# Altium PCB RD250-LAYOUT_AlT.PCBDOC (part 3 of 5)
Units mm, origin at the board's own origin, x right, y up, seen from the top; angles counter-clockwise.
Board outline 318.5 x 135 mm, 6 copper layers (TOP, Mid-Layer 1, Mid-Layer 2, Mid-Layer 3, Mid-Layer 4, BOTTOM), stack 1.422 mm thick; 550 components, 251 nets, 1350 pads, 626 vias.
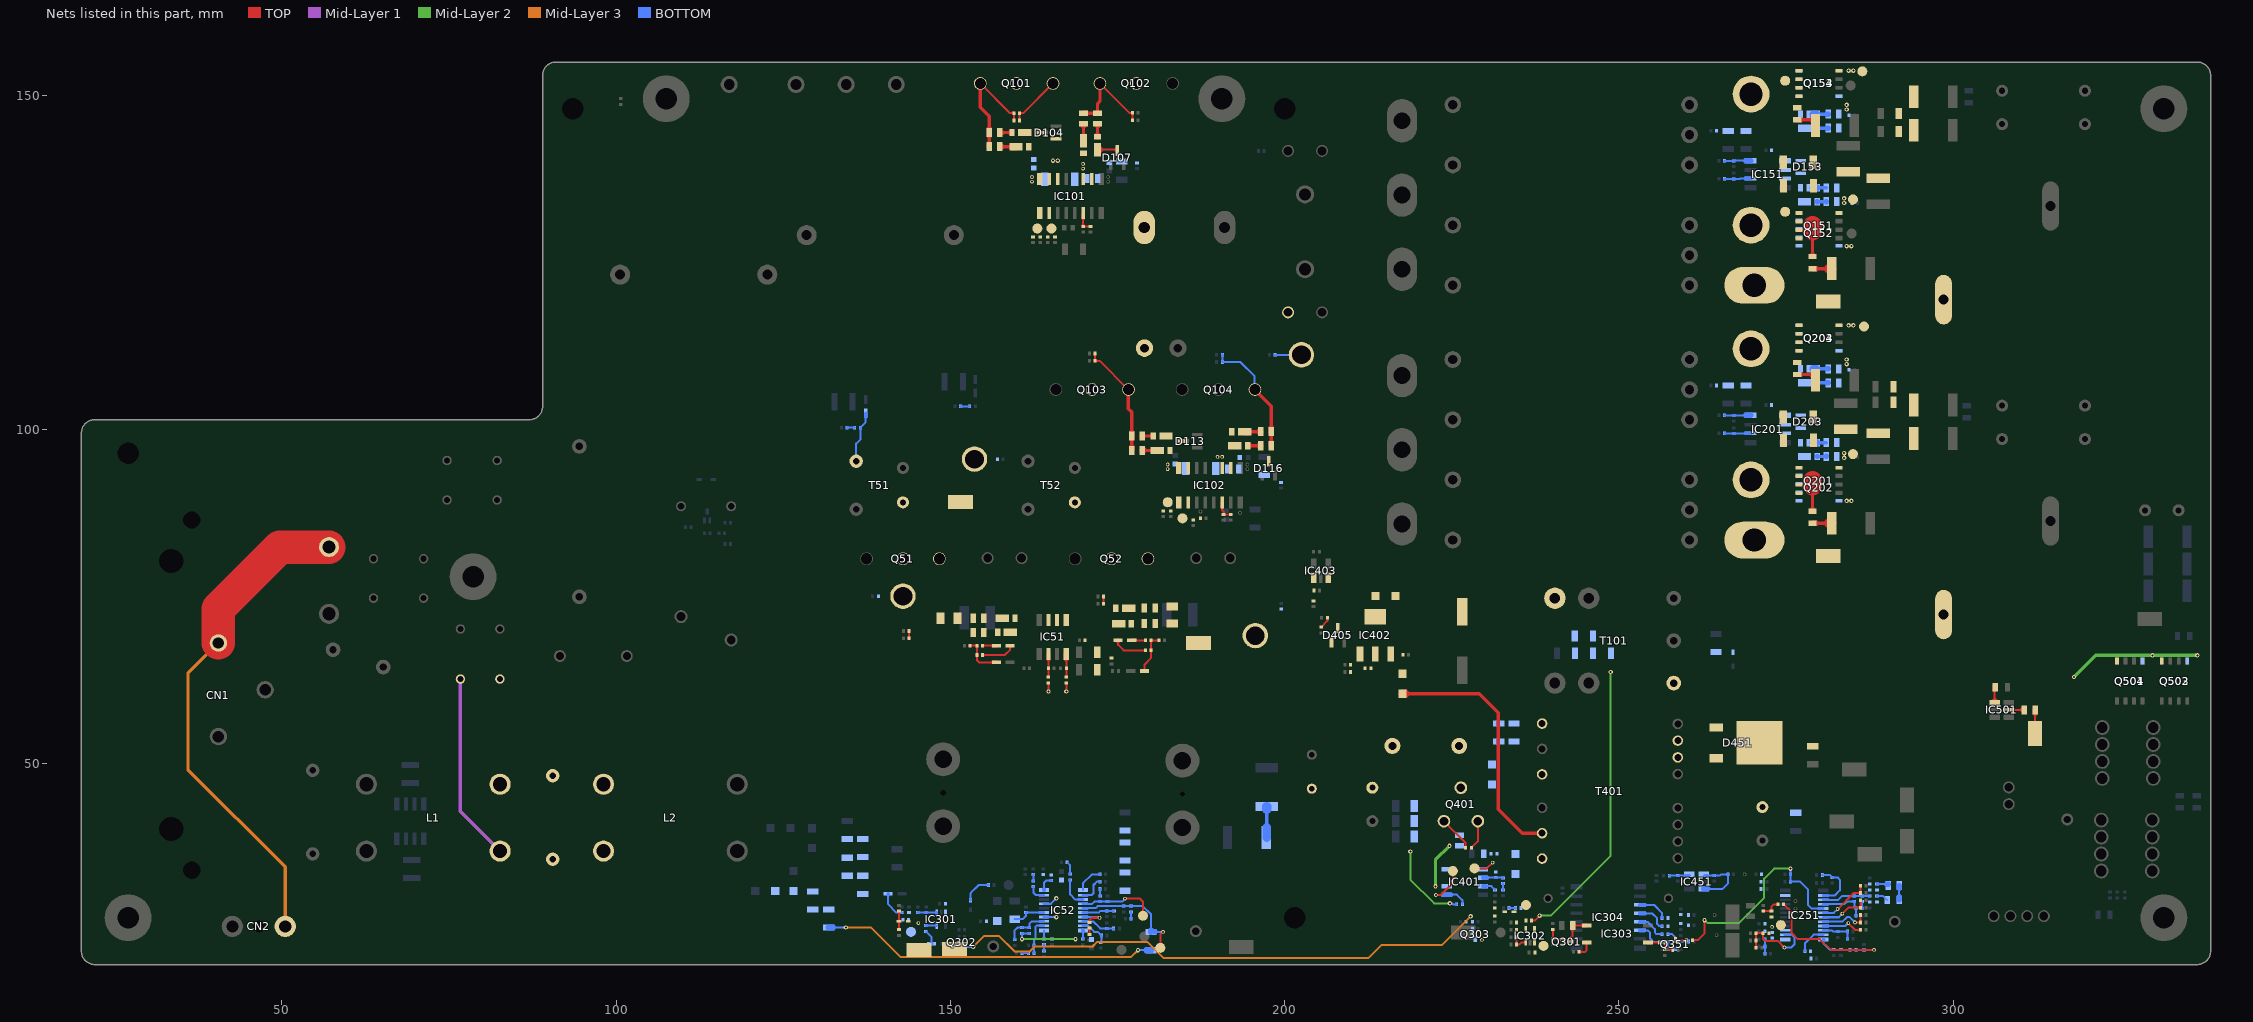
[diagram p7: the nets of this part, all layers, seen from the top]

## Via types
v1: diameter 0.65, hole 0.3, TOP to BOTTOM, 626 vias

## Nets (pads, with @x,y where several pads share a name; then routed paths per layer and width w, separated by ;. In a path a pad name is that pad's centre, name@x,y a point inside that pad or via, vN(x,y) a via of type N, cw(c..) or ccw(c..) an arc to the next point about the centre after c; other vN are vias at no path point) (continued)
SIG16: C60.2 R61.1 | length 1.3
  BOTTOM w0.3: C60.2@151.703,103.5 R61.1@152.697,103.5
  BOTTOM w0.45: C60.2@151.525,103.5 C60.2@151.703,103.5 ; R61.1@152.697,103.5 R61.1@152.875,103.5
SIG18: Q52.D T52.3
SIG20: D58.A R53.2 T51.1 | length 7.8
  BOTTOM w0.3: T51.1@135.9,95.3 135.9,97.9 136.525,98.525 R53.2@136.525,100.122 ; R53.2@136.525,100.3 137.31,101.085 D58.A@137.31,101.873
  BOTTOM w0.45: R53.2@136.525,100.122 R53.2@136.525,100.3
  BOTTOM w0.55: D58.A@137.31,101.873 D58.A@137.31,102.475
SIG21: C58.2 R53.1 | length 1.2
  BOTTOM w0.3: C58.2@134.703,100.3 R53.1@135.497,100.3
  BOTTOM w0.45: C58.2@134.525,100.3 C58.2@134.703,100.3 ; R53.1@135.497,100.3 R53.1@135.675,100.3
SIG22: Q51.D T51.3
SIG0022: C54.2 IC51.2 R97.2 | length 3.5
  TOP w0.3: C54.2@164.665,64.443 IC51.2@164.665,65.623 ; R97.2@164.675,63.163 C54.2@164.675,64.122
  TOP w0.43: C54.2@164.665,64.26 C54.2@164.665,64.443
  TOP w0.45: R97.2@164.675,62.975 R97.2@164.675,63.163 ; C54.2@164.675,64.122 C54.2@164.675,64.3
  TOP w0.55: IC51.2@164.665,65.623 IC51.2@164.665,66.443
SIG23: L54.1 R62.2 R63.2
SIG0023: C53.2 IC51.4 R98.2 | length 3.5
  TOP w0.3: R98.2@167.325,63.163 C53.2@167.325,64.122 ; C53.2@167.342,64.446 IC51.4@167.342,65.772
  TOP w0.415: C53.2@167.342,64.267 C53.2@167.342,64.446
  TOP w0.45: R98.2@167.325,62.975 R98.2@167.325,63.163 ; C53.2@167.325,64.122 C53.2@167.325,64.3
  TOP w0.825: IC51.4@167.342,65.772 IC51.4@167.342,66.443
SIG24: C61.2 D67.A R65.2 R66.2 | length 6.2
  TOP w0.3: D67.A@179.025,64.01 179.025,64.875 180.025,65.875 R65.2@180.025,66.822 ; R65.2@180.025,67.178 R66.2@180.025,68.322 ; R66.2@180.203,68.5 C61.2@180.997,68.5
  TOP w0.45: R65.2@180.025,66.822 R65.2@180.025,67 R65.2@180.025,67.178 ; R66.2@180.025,68.322 R66.2@180.025,68.5 R66.2@180.203,68.5 ; C61.2@180.997,68.5 C61.2@181.175,68.5
  TOP w0.55: D67.A@179.025,63.9 D67.A@179.025,64.01
SIG0024: C76.1 R91.2 | length 2
  BOTTOM w0.3: R91.2@167.425,35.3 167.9,34.825 C76.1@167.9,33.653
  BOTTOM w0.45: C76.1@167.9,33.525 C76.1@167.9,33.653
SIG25: C59.2 D62.A R57.2 R58.2 | length 6.3
  TOP w0.3: C59.2@153.09,67.7 R58.2@153.81,67.7 ; R57.2@153.975,66.122 153.975,65.5 154.275,65.2 D62.A@156.273,65.2 ; R57.2@153.975,66.478 R58.2@153.975,67.522
  TOP w0.45: C59.2@152.925,67.7 C59.2@153.09,67.7 ; R58.2@153.81,67.7 R58.2@153.975,67.7 R58.2@153.975,67.522 ; R57.2@153.975,66.122 R57.2@153.975,66.3 R57.2@153.975,66.478
  TOP w0.55: D62.A@156.273,65.2 D62.A@156.875,65.2
SIG0025: C74.1 R90.2 | length 1
  BOTTOM w0.3: R90.2@160.84,21.7 C74.1@161.56,21.7
  BOTTOM w0.45: R90.2@160.725,21.7 R90.2@160.84,21.7 ; C74.1@161.56,21.7 C74.1@161.675,21.7
SIG0026: C70.2 IC52.13 R86.2 R87.2 | length 6.7
  BOTTOM w0.3: C70.2@159.6,23.903 159.6,25.1 160.025,25.525 R86.2@160.7,25.525 ; R86.2@160.878,25.525 R87.2@161.622,25.525 ; R87.2@161.8,25.703 161.8,26.1 162.175,26.475 IC52.13@163.343,26.475
  BOTTOM w0.4: IC52.13@163.343,26.475 IC52.13@163.975,26.475
  BOTTOM w0.45: C70.2@159.6,23.725 C70.2@159.6,23.903 ; R86.2@160.7,25.525 R86.2@160.878,25.525 ; R87.2@161.622,25.525 R87.2@161.8,25.525 R87.2@161.8,25.703
SIG27: L53.1 R54.2 R55.2
SIG0027: C67.2 C68.2 D68.C IC52.15 R85.2 | length 5.1
  BOTTOM w0.3: C67.2@159.6,26.8 160.8,26.8 161.3,27.3 C68.2@161.3,27.66 ; C68.2@161.478,27.775 IC52.15@163.276,27.775
  BOTTOM w0.4: IC52.15@163.276,27.775 IC52.15@163.975,27.775
  BOTTOM w0.45: C68.2@161.3,27.66 C68.2@161.3,27.775 C68.2@161.478,27.775
SIG0028: R83.1 R84.2 | length 1
  BOTTOM w0.3: R83.1@162.4,32.64 R84.2@162.4,33.36
  BOTTOM w0.45: R83.1@162.4,32.525 R83.1@162.4,32.64 ; R84.2@162.4,33.36 R84.2@162.4,33.475
SIG0029: IC52.19 R83.2 | length 2.6
  BOTTOM w0.3: R83.2@162.4,31.585 162.4,30.775 162.8,30.375 IC52.19@163.276,30.375
  BOTTOM w0.4: IC52.19@163.276,30.375 IC52.19@163.975,30.375
  BOTTOM w0.45: R83.2@162.4,31.585 R83.2@162.4,31.675
SIG30: D59.A D60.C D61.C IC51.7 R57.1 | length 5
  TOP w0.3: R57.1@155.003,66.3 158.125,66.3 158.925,67.1 D61.C@158.925,67.54
  TOP w0.45: R57.1@154.825,66.3 R57.1@155.003,66.3
  TOP w0.55: D61.C@158.925,67.54 D61.C@158.925,67.7
SIG0057: IC251.2 R272.1 R273.2 | length 7.3
  BOTTOM w0.3: R273.2@280.603,33.4 281.525,33.4 R272.1@281.9,33.025 ; IC251.2@281.324,30.325 282.275,30.325 283.05,31.1 283.05,32.675 282.7,33.025 R272.1@282.078,33.025
  BOTTOM w0.4: IC251.2@280.562,30.325 IC251.2@281.324,30.325
  BOTTOM w0.45: R273.2@280.425,33.4 R273.2@280.603,33.4 ; R272.1@281.9,33.025 R272.1@282.078,33.025
SIG0058: C256.1 R286.1 | length 1
  BOTTOM w0.3: C256.1@286.325,28.553 R286.1@286.325,29.312
  BOTTOM w0.4: R286.1@286.325,29.312 R286.1@286.325,29.425
  BOTTOM w0.45: C256.1@286.325,28.4 C256.1@286.325,28.553
SIG0059: C257.1 C258.1 IC251.3 R286.2 R289.1 R290.2 | length 8.9
  BOTTOM w0.3: IC251.3@281.324,29.675 282.775,29.675 283.375,30.275 C257.1@285.022,30.275 ; C257.1@285.378,30.275 R286.2@286.222,30.275 ; R286.2@286.578,30.275 R289.1@287.322,30.275 ; R290.2@288.703,30.225 289.525,30.225 C258.1@290.1,29.65
  BOTTOM w0.4: IC251.3@280.562,29.675 IC251.3@281.324,29.675
  BOTTOM w0.45: C257.1@285.022,30.275 C257.1@285.2,30.275 C257.1@285.378,30.275 ; R286.2@286.222,30.275 R286.2@286.4,30.275 R286.2@286.578,30.275 ; R289.1@287.322,30.275 R289.1@287.5,30.275 ; R290.2@288.6,30.225 R290.2@288.703,30.225
SIG100: D64.C R63.1
SIG101: D65.A R62.1
SIG102: D64.A D65.C D66.C IC51.5 R65.1 | length 5.1
  TOP w0.3: D66.C@175.075,68.303 175.075,67.825 175.9,67 R65.1@178.997,67
  TOP w0.45: R65.1@178.997,67 R65.1@179.175,67
  TOP w0.55: D66.C@175.075,68.303 D66.C@175.075,68.5
SIG104: C55.2 C56.2 C57.2 IC51.6 R51.2
SIG105: D60.A R54.1
SIG106: D59.C R55.1
SIG115: C204.2 CN201.1 D207.A Q201.5 Q201.6 Q201.7 Q201.8 Q202.5 Q202.6 Q202.7 Q202.8 | length 4.6
  TOP w0.5: C204.2@278.95,88.106 278.95,91.646
  TOP w0.8: C204.2@278.95,87.8 C204.2@278.95,88.106
  TOP w2.9: 278.95,91.646 278.95,92.4
SIG122: C509.1 IC501.1 | length 2.5
  TOP w0.3: IC501.1@306.175,59.436 C509.1@306.175,60.938
  TOP w0.55: C509.1@306.175,60.938 C509.1@306.175,61.7
  TOP w0.825: IC501.1@306.175,59.187 IC501.1@306.175,59.436
SIG136: IC501.5 R504.1 | length 2.3
  TOP w0.3: IC501.5@309.027,58.1 R504.1@310.401,58.1
  TOP w0.55: IC501.5@308.325,58.1 IC501.5@309.027,58.1
  TOP w0.83: R504.1@310.401,58.1 R504.1@310.65,58.1
SIG141: DP502.1 Q501.4 Q502.4 Q503.4 Q504.4 R504.2 | length 23.3
  TOP w0.3: DP502.1@312.25,55.35 R504.2@312.25,57.591
  TOP w0.83: R504.2@312.25,57.591 R504.2@312.25,58.1
  TOP w2.1: DP502.1@312.25,54.55 DP502.1@312.25,55.35
  Mid-Layer 2 w0.5: v1(318.05,63) 321.3,66.25 v1(329.8,66.25) v1(336.5,66.25)
SIG193: CN1.1 CN2.1 F1.1 | length 75.8
  TOP w5: CN1.1@40.5,68.1 40.5,73.25 49.7,82.45 F1.1@57.05,82.45
  Mid-Layer 3 w0.5: CN1.1@40.5,68.1 35.95,63.55 35.95,49.15 50.5,34.6 CN2.1@50.5,25.7
SIG199: C4.2 C6.2 L1.2 L2.1
SIG200: C5.2 C6.1 L1.3 L2.4 | length 28.2
  Mid-Layer 1 w0.5: C5.2@76.7,62.7 76.7,42.913 80.363,39.25 L1.3@82.643,36.97
SIG00210: R93.1 R94.2
SIG00211: C64.2 DP56.1 IC52.5 pad.@181.8,24.9 R72.1 R73.2 | length 17.8
  TOP w0.3: DP56.1@181.4,22.5 181.4,24.484 cw(c181.438,24.484) 181.411,24.511 pad.@181.8,24.9
  BOTTOM w0.3: IC52.5@170.524,28.425 171.725,28.425 172.025,28.725 C64.2@175.71,28.725 ; C64.2@175.978,28.725 R73.2@176.822,28.725 ; R73.2@177.178,28.725 178.775,28.725 180,27.5 R72.1@180,25.116 ; R72.1@180.54,24.9 pad.@181.8,24.9
  BOTTOM w0.4: IC52.5@169.825,28.425 IC52.5@170.524,28.425
  BOTTOM w0.45: C64.2@175.71,28.725 C64.2@175.9,28.725 C64.2@175.978,28.725 ; R73.2@176.822,28.725 R73.2@177,28.725 R73.2@177.178,28.725
  BOTTOM w0.82: R72.1@180.05,24.9 R72.1@180.54,24.9
  BOTTOM w0.92: R72.1@180,24.85 R72.1@180,25.116
SIG00212: R95.1 R96.2 | length 1
  BOTTOM w0.3: R95.1@172.4,30.428 R96.2@172.4,31.187
  BOTTOM w0.4: R96.2@172.4,31.187 R96.2@172.4,31.3
  BOTTOM w0.45: R95.1@172.4,30.275 R95.1@172.4,30.428
SIG00213: IC52.7 pad.@172.3,27 R81.2 | length 4.5
  TOP w0.3: R81.2@170.8,26.325 170.8,26.652 171.148,27 pad.@172.3,27
  BOTTOM w0.3: IC52.7@170.524,27.125 171.6,27.125 171.725,27 pad.@172.3,27
  BOTTOM w0.4: IC52.7@169.825,27.125 IC52.7@170.524,27.125
SIG00214: C77.2 DP60.1 IC52.4 pad.@176.1,29.85 R94.1 R95.2 | length 11.6
  TOP w0.3: pad.@176.1,29.85 178.35,29.85 178.8,29.4 DP60.1@178.8,27.3
  BOTTOM w0.3: IC52.4@170.482,29.075 171.2,29.075 171.55,29.425 R95.2@172.222,29.425 ; R95.2@172.578,29.425 C77.2@173.322,29.425 ; C77.2@173.615,29.425 175.675,29.425 pad.@176.1,29.85
  BOTTOM w0.4: IC52.4@169.825,29.075 IC52.4@170.482,29.075
  BOTTOM w0.45: R95.2@172.222,29.425 R95.2@172.4,29.425 R95.2@172.578,29.425 ; C77.2@173.322,29.425 C77.2@173.5,29.425 C77.2@173.615,29.425
SIG00215: R81.1 R82.2 | length 1
  TOP w0.3: R82.2@170.8,24.64 R81.1@170.8,25.36
  TOP w0.45: R82.2@170.8,24.525 R82.2@170.8,24.64 ; R81.1@170.8,25.36 R81.1@170.8,25.475
SIG00216: R77.1 R78.2
SIG00217: R73.1 R74.2 | length 1
  BOTTOM w0.3: R74.2@177.025,27.003 R73.1@177.025,27.812
  BOTTOM w0.45: R74.2@177.025,26.85 R74.2@177.025,27.003 ; R73.1@177.025,27.812 R73.1@177.025,27.875
SIG00218: R70.1 R71.2
SIG00219: C69.2 IC52.10 R86.1 R87.1 R88.2 | length 11.2
  Mid-Layer 2 w0.3: v1(160.7,23.8) v1(168.7,23.8)
  BOTTOM w0.3: v1(160.7,23.8) R86.1@160.7,24.597 ; R86.1@160.878,24.675 R87.1@161.622,24.675 ; R88.2@169.825,24.025 IC52.10@169.825,24.943
  BOTTOM w0.4: R88.2@169.825,23.85 R88.2@169.825,24.025
  BOTTOM w0.45: R86.1@160.7,24.597 R86.1@160.7,24.675 R86.1@160.878,24.675 ; R87.1@161.622,24.675 R87.1@161.8,24.675
  BOTTOM w0.6: IC52.10@169.825,24.943 IC52.10@169.825,25.075
SIG00220: C73.2 C74.2 IC52.12 | length 5.4
  BOTTOM w0.3: C74.2@162.525,21.878 C73.2@162.525,22.722 ; C73.2@162.525,22.902 162.525,23.625 162.7,23.8 162.7,25.625 162.9,25.825 IC52.12@163.276,25.825
  BOTTOM w0.4: IC52.12@163.276,25.825 IC52.12@163.975,25.825
  BOTTOM w0.45: C74.2@162.525,21.7 C74.2@162.525,21.878 ; C73.2@162.525,22.722 C73.2@162.525,22.9 C73.2@162.525,22.902
SIG00221: C71.2 C72.2 IC52.11 | length 2.5
  BOTTOM w0.3: IC52.11@163.975,25.075 163.975,24.125 164,24.1 C72.2@164,23.825 ; C72.2@164.178,23.825 C71.2@165.022,23.825
  BOTTOM w0.45: C72.2@164,23.825 C72.2@164.178,23.825 ; C71.2@165.022,23.825 C71.2@165.2,23.825
SIG00222: R71.1 R72.2 | length 50.5
  Mid-Layer 3 w0.3: v1(134.35,25.55) 138.1,25.55 142.55,21.1 177,21.1 v1(178.05,22.15)
  BOTTOM w0.3: R71.1@132.456,25.55 v1(134.35,25.55) ; v1(178.05,22.15) R72.2@179.344,22.15
  BOTTOM w0.92: R71.1@131.8,25.55 R71.1@132.456,25.55 ; R72.2@179.344,22.15 R72.2@180,22.15
SIG00223: IC52.6 R79.2 R80.2 | length 4.7
  BOTTOM w0.3: IC52.6@170.458,27.775 172.175,27.775 172.425,28.025 R79.2@173.222,28.025 ; R79.2@173.573,28.025 R80.2@174.227,28.025
  BOTTOM w0.4: IC52.6@169.825,27.775 IC52.6@170.458,27.775
  BOTTOM w0.45: R79.2@173.222,28.025 R79.2@173.4,28.025 R79.2@173.573,28.025 ; R80.2@174.227,28.025 R80.2@174.4,28.025
SIG00224: IC52.20 R77.2 | length 2.4
  BOTTOM w0.3: IC52.20@163.975,31.331 163.975,32.2 164.35,32.575 R77.2@164.922,32.575
  BOTTOM w0.45: R77.2@164.922,32.575 R77.2@165.1,32.575
  BOTTOM w0.6: IC52.20@163.975,31.125 IC52.20@163.975,31.331
SIG00225: C63.2 IC52.8 R69.2 | length 5.1
  BOTTOM w0.3: IC52.8@170.524,26.475 171.325,26.475 172.4,25.4 C63.2@173.37,25.4 ; C63.2@173.565,25.375 R69.2@174.325,25.375
  BOTTOM w0.4: IC52.8@169.825,26.475 IC52.8@170.524,26.475 ; C63.2@173.37,25.4 C63.2@173.4,25.4 ; R69.2@174.325,25.375 R69.2@174.45,25.375
  BOTTOM w0.45: C63.2@173.4,25.375 C63.2@173.565,25.375
SIG00226: C65.2 IC52.1 | length 4.1
  BOTTOM w0.3: IC52.1@169.825,31.125 169.825,32.08 cw(c170.025,32.08) 169.884,32.221 171.104,33.442 cw(c171.245,33.3) 171.245,33.5 C65.2@172.187,33.5
  BOTTOM w0.45: C65.2@172.187,33.5 C65.2@172.375,33.5
SIG00227: R92.1 R93.2
SIG00228: IC52.2 R76.2 | length 4.1
  BOTTOM w0.3: IC52.2@170.524,30.375 171.1,30.375 171.4,30.675 171.4,31.9 171.9,32.4 R76.2@172.347,32.4
  BOTTOM w0.4: IC52.2@169.825,30.375 IC52.2@170.524,30.375
  BOTTOM w0.45: R76.2@172.347,32.4 R76.2@172.375,32.4
SIG00229: C75.2 C76.2 IC52.3 | length 4.4
  BOTTOM w0.3: C76.2@167.9,32.497 167.9,30.5 168.675,29.725 IC52.3@169.126,29.725
  BOTTOM w0.4: IC52.3@169.126,29.725 IC52.3@169.825,29.725
  BOTTOM w0.45: C76.2@167.9,32.497 C76.2@167.9,32.675
SIG00230: C72.1 R89.2 | length 1
  BOTTOM w0.3: R89.2@164,22.14 C72.1@164,22.86
  BOTTOM w0.45: R89.2@164,22.025 R89.2@164,22.14 ; C72.1@164,22.86 C72.1@164,22.975
SIG00231: C62.2 IC52.9 R68.2 | length 4.4
  BOTTOM w0.3: IC52.9@170.355,25.825 170.575,25.825 171.5,24.9 172.025,24.9 R68.2@172.575,24.35 ; C62.2@172.575,23.437 R68.2@172.575,24.198
  BOTTOM w0.4: IC52.9@169.825,25.825 IC52.9@170.355,25.825 ; C62.2@172.575,23.325 C62.2@172.575,23.437
  BOTTOM w0.45: R68.2@172.575,24.198 R68.2@172.575,24.35
SIG00232: D53.C D54.C R70.2
SIG00233: DP57.1 IC52.17 R98.1 | length 3.5
  TOP w0.3: v1(167.325,60.85) R98.1@167.325,61.938
  TOP w0.45: R98.1@167.325,61.938 R98.1@167.325,62.125
  BOTTOM w0.3: IC52.17@164.674,29.075 165.025,29.075 v1(165.85,29.9)
  BOTTOM w0.4: IC52.17@163.975,29.075 IC52.17@164.674,29.075
SIG00234: DP58.1 IC52.14 R97.1 | length 3.2
  TOP w0.3: v1(164.675,60.85) R97.1@164.675,61.938
  TOP w0.45: R97.1@164.675,61.938 R97.1@164.675,62.125
  BOTTOM w0.3: IC52.14@164.505,27.125 164.975,27.125 165,27.1 v1(165.85,27.1)
  BOTTOM w0.4: IC52.14@163.975,27.125 IC52.14@164.505,27.125
SIG00331: R101.1 R102.2 | length 4.6
  BOTTOM w0.5: R102.2@197.3,40.498 R101.1@197.3,43.228
  BOTTOM w1.31: R102.2@197.3,39 R102.2@197.3,40.498
  BOTTOM w1.405: R101.1@197.3,43.228 R101.1@197.3,43.647
SIG00332: D251.A R251.2 T101.5
SIG00333: D105.A D106.C D107.C IC101.10 | length 3
  TOP w0.3: D106.C@172.3,141.9 D107.C@174.737,141.9
  TOP w0.55: D107.C@174.737,141.9 D107.C@174.95,141.9
  TOP w1.1: D106.C@172,141.9 D106.C@172.3,141.9
SIG00334: C108.2 D101.C IC101.16 pad.@162.2,137.1 pad.@162.2,137.8
SIG00335: D101.A R107.1
SIG00336: C106.2 C107.2 IC101.11 pad.@169.85,139.05 pad.@169.85,139.75 R106.2 R107.2
SIG00337: D105.C R111.1 | length 2.5
  TOP w0.5: D105.C@169.9,143.845 R111.1@169.9,145.438
  TOP w0.83: R111.1@169.9,145.438 R111.1@169.9,145.75
  TOP w1.1: D105.C@169.9,143.25 D105.C@169.9,143.845
SIG00338: D106.A R112.1 | length 2
  TOP w0.5: D106.A@172,144.106 R112.1@172,145.439
  TOP w0.8: D106.A@172,143.8 D106.A@172,144.106
  TOP w0.83: R112.1@172,145.439 R112.1@172,145.75
SIG00339: D102.A D103.C D104.C IC101.15
SIG00340: D103.A R109.1 | length 1.8
  TOP w0.5: R109.1@157.636,144.45 D103.A@158.94,144.45
  TOP w0.8: D103.A@158.94,144.45 D103.A@159.2,144.45
  TOP w0.83: R109.1@157.4,144.45 R109.1@157.636,144.45
SIG00341: D102.C R108.1 | length 2.4
  TOP w0.5: R108.1@157.712,142.35 D102.C@159.256,142.35
  TOP w0.83: R108.1@157.4,142.35 R108.1@157.712,142.35
  TOP w1.1: D102.C@159.256,142.35 D102.C@159.8,142.35
SIG00342: C110.2 Q102.G R111.2 R112.2 R113.2 | length 14.5
  TOP w0.3: Q102.G@172.36,151.8 176.76,147.4 C110.2@177.047,147.4 ; R113.2@177.225,146.478 C110.2@177.225,147.222
  TOP w0.45: C110.2@177.047,147.4 C110.2@177.225,147.4 C110.2@177.225,147.222 ; R113.2@177.225,146.3 R113.2@177.225,146.478
  TOP w0.5: R111.2@170.416,147.35 R112.2@171.74,147.35 ; R112.2@172,147.486 172,148.75 172.36,149.11 Q102.G@172.36,151.8
  TOP w0.83: R111.2@169.9,147.35 R111.2@170.416,147.35 ; R112.2@171.74,147.35 R112.2@172,147.35 R112.2@172,147.486
SIG00343: C111.2 D108.C Q101.D Q103.D T101.1
SIG00344: D111.C R119.1 | length 2.2
  TOP w0.5: R119.1@179.012,96.9 D111.C@180.5,96.9
  TOP w0.83: R119.1@178.7,96.9 R119.1@179.012,96.9
  TOP w1.1: D111.C@180.5,96.9 D111.C@180.95,96.9
SIG00345: C119.2 D110.C IC102.16 pad.@182.5,94.1 pad.@182.5,94.8
SIG00346: D114.A D115.C D116.C IC102.10
SIG00347: D111.A D112.C D113.C IC102.15
SIG00348: C114.2 IC102.6 R116.1 | length 3
  TOP w0.3: IC102.6@190.655,88.378 190.655,87.939 190.85,87.743 R116.1@190.85,87.325 ; R116.1@191.028,87.325 C114.2@191.772,87.325
  TOP w0.45: R116.1@190.85,87.325 R116.1@191.028,87.325 ; C114.2@191.772,87.325 C114.2@191.95,87.325
  TOP w0.55: IC102.6@190.655,88.378 IC102.6@190.655,89.142
SIG00349: D114.C R122.1 | length 2.4
  TOP w0.5: D114.C@194.545,99.7 R122.1@196.089,99.7
  TOP w0.83: R122.1@196.089,99.7 R122.1@196.4,99.7
  TOP w1.1: D114.C@194,99.7 D114.C@194.545,99.7
SIG00350: D115.A R123.1 | length 2
  TOP w0.5: D115.A@194.756,97.6 R123.1@196.088,97.6
  TOP w0.8: D115.A@194.45,97.6 D115.A@194.756,97.6
  TOP w0.83: R123.1@196.088,97.6 R123.1@196.4,97.6
SIG00351: C120.2 Q103.G R119.2 R120.2 R121.2 | length 17.2
  TOP w0.3: C120.2@171.625,110.478 R121.2@171.625,111.222 ; C120.2@171.803,110.3 172.3,110.3 Q103.G@176.6,106
  TOP w0.45: C120.2@171.625,110.478 C120.2@171.625,110.3 C120.2@171.803,110.3 ; R121.2@171.625,111.222 R121.2@171.625,111.4
  TOP w0.5: Q103.G@176.6,106 176.6,103.15 177.1,102.65 R120.2@177.1,99.622 ; R119.2@177.1,97.441 R120.2@177.1,98.769
  TOP w0.83: R119.2@177.1,96.9 R119.2@177.1,97.441 ; R120.2@177.1,98.769 R120.2@177.1,99.05 R120.2@177.1,99.622
SIG00352: C121.2 Q104.G R122.2 R123.2 R124.2 | length 18.2
  TOP w0.5: Q104.G@195.5,106 198,103.5 R122.2@198,100.272 ; R123.2@198,98.116 R122.2@198,99.44
  TOP w0.83: R123.2@198,97.6 R123.2@198,98.116 ; R122.2@198,99.44 R122.2@198,99.7 R122.2@198,100.272
  BOTTOM w0.3: C121.2@190.675,110.303 R124.2@190.675,111.047 ; C121.2@190.853,110.125 193.375,110.125 195.5,108 Q104.G@195.5,106
  BOTTOM w0.45: C121.2@190.675,110.303 C121.2@190.675,110.125 C121.2@190.853,110.125 ; R124.2@190.675,111.047 R124.2@190.675,111.225
SIG00353: C117.2 C118.2 IC102.11 pad.@189.95,95.95 pad.@190.65,95.95 R117.2 R118.2
SIG00354: D110.A R118.1
SIG00355: D112.A R120.1 | length 1.6
  TOP w0.5: R120.1@178.861,99.05 D112.A@180.165,99.05
  TOP w0.8: D112.A@180.165,99.05 D112.A@180.35,99.05
  TOP w0.83: R120.1@178.7,99.05 R120.1@178.861,99.05
SIG00356: C109.2 Q101.G R108.2 R109.2 R110.2 | length 18
  TOP w0.3: Q101.G@154.46,151.8 158.91,147.35 C109.2@159.297,147.35 ; R110.2@159.475,146.428 C109.2@159.475,147.172
  TOP w0.45: C109.2@159.297,147.35 C109.2@159.475,147.35 C109.2@159.475,147.172 ; R110.2@159.475,146.25 R110.2@159.475,146.428
  TOP w0.5: Q101.G@154.46,151.8 154.46,148.25 155.8,146.91 R109.2@155.8,145.022 ; R108.2@155.8,142.61 R109.2@155.8,143.934
  TOP w0.83: R108.2@155.8,142.35 R108.2@155.8,142.61 ; R109.2@155.8,143.934 R109.2@155.8,144.45 R109.2@155.8,145.022
SIG00357: C103.2 IC101.6 R105.1 | length 3.1
  TOP w0.3: R105.1@169.855,130.615 IC101.6@169.855,131.573 ; R105.1@170.028,130.425 C103.2@170.772,130.425
  TOP w0.44: R105.1@169.855,130.43 R105.1@169.855,130.615
  TOP w0.45: R105.1@169.85,130.425 R105.1@170.028,130.425 ; C103.2@170.772,130.425 C103.2@170.95,130.425
  TOP w0.55: IC101.6@169.855,131.573 IC101.6@169.855,132.392
SIG00358: C102.2 DP101.1 IC101.1 R104.1
SIG00359: C101.2 DP102.1 IC101.2 R103.1
SIG00360: C113.2 DP103.1 IC102.1 R115.1
SIG00361: C112.2 DP104.1 IC102.2 R114.1
SIG00362: C108.1 C109.1 D104.A IC101.14 L101.1 Q101.S Q102.D R110.1 | length 8
  TOP w0.3: R110.1@160.325,146.428 C109.1@160.325,147.172 ; C109.1@160.503,147.35 160.89,147.35 Q101.S@165.34,151.8
  TOP w0.45: R110.1@160.325,146.25 R110.1@160.325,146.428 ; C109.1@160.325,147.172 C109.1@160.325,147.35 C109.1@160.503,147.35
  other v1: 165.35,140.25 166.05,140.25
SIG00429: C151.2 C152.2 C153.2 IC151.6 R151.2
SIG00430: D151.C R152.1 | length 1.9
  BOTTOM w0.5: D151.C@279.5,136.175 R152.1@281,136.175
  BOTTOM w1.1: D151.C@279.05,136.175 D151.C@279.5,136.175
SIG00431: D152.A R153.1 | length 1.3
  BOTTOM w0.5: D152.A@279.685,134.1 R153.1@280.989,134.1
  BOTTOM w0.8: D152.A@279.65,134.1 D152.A@279.685,134.1
  BOTTOM w0.83: R153.1@280.989,134.1 R153.1@281,134.1
SIG00432: D154.C R156.1 | length 2.2
  BOTTOM w0.5: D154.C@279.52,147.2 R156.1@281.064,147.2
  BOTTOM w0.83: R156.1@281.064,147.2 R156.1@281.3,147.2
  BOTTOM w1.1: D154.C@279.05,147.2 D154.C@279.52,147.2
SIG00433: D156.A R157.1 | length 1.6
  BOTTOM w0.5: D156.A@279.835,145.1 R157.1@281.139,145.1
  BOTTOM w0.8: D156.A@279.65,145.1 D156.A@279.835,145.1
  BOTTOM w0.83: R157.1@281.139,145.1 R157.1@281.3,145.1
SIG00434: D201.C R202.1 | length 1.9
  BOTTOM w0.5: D201.C@279.5,98.075 R202.1@281,98.075
  BOTTOM w1.1: D201.C@279.05,98.075 D201.C@279.5,98.075
SIG00435: D202.A R203.1 | length 1.3
  BOTTOM w0.5: D202.A@279.685,96 R203.1@280.989,96
  BOTTOM w0.8: D202.A@279.65,96 D202.A@279.685,96
  BOTTOM w0.83: R203.1@280.989,96 R203.1@281,96
SIG00436: D204.C R206.1 | length 2.2
  BOTTOM w0.5: D204.C@279.52,109.1 R206.1@281.064,109.1
  BOTTOM w0.83: R206.1@281.064,109.1 R206.1@281.3,109.1
  BOTTOM w1.1: D204.C@279.05,109.1 D204.C@279.52,109.1
SIG00437: D206.A R207.1 | length 1.6
  BOTTOM w0.5: D206.A@279.835,107 R207.1@281.139,107
  BOTTOM w0.8: D206.A@279.65,107 D206.A@279.835,107
  BOTTOM w0.83: R207.1@281.139,107 R207.1@281.3,107
SIG00438: D201.A D202.C D203.A IC201.7
SIG00439: DP155.1 Q153.4 Q154.4 R156.2 R157.2 R158.2
  other v1: 284.05,147.9 284.05,148.6 284.35,153.7 285.05,153.7
SIG00440: DP202.1 Q203.4 Q204.4 R206.2 R207.2 R208.2
  other v1: 284.05,109.8 284.05,110.5 284.35,115.6 285.05,115.6
SIG00441: C154.1 R155.2 | length 2.8
  TOP w0.5: C154.1@279.481,124.1 R155.2@281.378,124.1
  TOP w0.8: C154.1@278.95,124.1 C154.1@279.481,124.1
  TOP w1.405: R155.2@281.378,124.1 R155.2@281.798,124.1
SIG00442: C155.1 R159.2 | length 2.7
  TOP w0.5: C155.1@277.181,146.35 R159.2@279.226,146.35
  TOP w0.8: C155.1@276.65,146.35 C155.1@277.181,146.35
  TOP w1.405: R159.2@279.226,146.35 R159.2@279.398,146.35
SIG00443: C205.1 R209.2 | length 2.7
  TOP w0.5: C205.1@277.181,108.25 R209.2@279.226,108.25
  TOP w0.8: C205.1@276.65,108.25 C205.1@277.181,108.25
  TOP w1.405: R209.2@279.226,108.25 R209.2@279.398,108.25
SIG00444: C204.1 R205.2 | length 2.8
  TOP w0.5: C204.1@279.481,86 R205.2@281.378,86
  TOP w0.8: C204.1@278.95,86 C204.1@279.481,86
  TOP w1.405: R205.2@281.378,86 R205.2@281.798,86
SIG00445: C205.2 CN202.1 D208.A Q203.5 Q203.6 Q203.7 Q203.8 Q204.5 Q204.6 Q204.7 Q204.8
SIG00446: CN153.1 DP157.1 L151.S
SIG00447: C154.2 CN151.1 D157.A DP151.1 Q151.5 Q151.6 Q151.7 Q151.8 Q152.5 Q152.6 Q152.7 Q152.8 | length 4.6
  TOP w0.5: C154.2@278.95,126.206 278.95,129.746
  TOP w0.8: C154.2@278.95,125.9 C154.2@278.95,126.206
  TOP w2.9: 278.95,129.746 278.95,130.5
SIG00448: CN203.1 DP203.1 L201.S
SIG00449: DP152.1 Q151.4 Q152.4 R152.2 R153.2 R154.2
  other v1: 284.05,127.45 284.75,127.45 283.69,133.9 283.69,134.6
SIG00450: DP201.1 Q201.4 Q202.4 R202.2 R203.2 R204.2
  other v1: 284.05,89.35 284.75,89.35 283.69,95.8 283.69,96.5
SIG00451: C158.2 IC151.2 R164.2 | length 3.9
  BOTTOM w0.3: R164.2@265.963,137.525 C158.2@266.972,137.525 ; C158.2@267.328,137.525 268.075,137.525 268.115,137.565 IC151.2@268.873,137.565
  BOTTOM w0.45: R164.2@265.775,137.525 R164.2@265.963,137.525 ; C158.2@266.972,137.525 C158.2@267.15,137.525 C158.2@267.328,137.525
  BOTTOM w0.55: IC151.2@268.873,137.565 IC151.2@269.693,137.565
SIG00452: C159.2 IC151.4 R165.2 | length 3.9
  BOTTOM w0.3: R165.2@265.963,140.225 C159.2@266.972,140.225 ; C159.2@267.322,140.243 IC151.4@268.959,140.243
  BOTTOM w0.415: C159.2@267.15,140.243 C159.2@267.322,140.243
  BOTTOM w0.45: R165.2@265.775,140.225 R165.2@265.963,140.225 ; C159.2@266.972,140.225 C159.2@267.15,140.225
  BOTTOM w0.825: IC151.4@268.959,140.243 IC151.4@269.693,140.243
SIG00453: C208.2 IC201.2 R214.2 | length 3.9
  BOTTOM w0.3: R214.2@265.963,99.425 C208.2@266.972,99.425 ; C208.2@267.328,99.425 268.075,99.425 268.115,99.465 IC201.2@268.873,99.465
  BOTTOM w0.45: R214.2@265.775,99.425 R214.2@265.963,99.425 ; C208.2@266.972,99.425 C208.2@267.15,99.425 C208.2@267.328,99.425
  BOTTOM w0.55: IC201.2@268.873,99.465 IC201.2@269.693,99.465
SIG00454: D153.NC D154.A D156.C IC151.5
SIG00455: D203.NC D204.A D206.C IC201.5
SIG00456: D151.A D152.C D153.A IC151.7
SIG00457: C155.2 CN152.1 D158.A DP154.1 Q153.5 Q153.6 Q153.7 Q153.8 Q154.5 Q154.6 Q154.7 Q154.8
SIG00458: C156.2 C157.2 D157.C D158.C R160.2 R161.2 R162.1 R163.1
SIG00459: C201.2 C202.2 C203.2 IC201.6 R201.2
SIG00460: C209.2 IC201.4 R215.2 | length 3.9
  BOTTOM w0.3: R215.2@265.963,102.125 C209.2@266.972,102.125 ; C209.2@267.322,102.143 IC201.4@268.959,102.143
  BOTTOM w0.415: C209.2@267.15,102.143 C209.2@267.322,102.143
  BOTTOM w0.45: R215.2@265.775,102.125 R215.2@265.963,102.125 ; C209.2@266.972,102.125 C209.2@267.15,102.125
  BOTTOM w0.825: IC201.4@268.959,102.143 IC201.4@269.693,102.143
SIG00461: C206.2 C207.2 D207.C D208.C R210.2 R211.2 R212.1 R213.1
SIG00510: R277.2 R278.2 R282.1 | length 3
  TOP w0.3: R282.1@271.778,27.975 R277.2@272.622,27.975 ; R277.2@272.8,28.028 272.8,28.65 273.15,29 R278.2@273.597,29
  TOP w0.45: R282.1@271.6,27.975 R282.1@271.778,27.975 ; R277.2@272.622,27.975 R277.2@272.8,27.975 R277.2@272.8,28.028 ; R278.2@273.597,29 R278.2@273.775,29
SIG00511: pad.@288.15,22.2 R278.1 R279.1 R280.2 | length 20.9
  TOP w0.3: R278.1@274.625,29 275.8,27.825 275.8,24.75 276.75,23.8 280.05,23.8 281.65,22.2 pad.@288.15,22.2
  BOTTOM w0.3: R280.2@285.603,22.2 R279.1@286.475,22.2 ; R279.1@286.828,22.175 pad.@288.15,22.175
  BOTTOM w0.4: R279.1@286.475,22.2 R279.1@286.65,22.2
  BOTTOM w0.45: R280.2@285.425,22.2 R280.2@285.603,22.2 ; R279.1@286.65,22.175 R279.1@286.828,22.175
SIG00512: C252.2 C253.2 IC251.23 R260.2
SIG00513: IC251.6 pad.@282.7,28.3 R253.2 R254.2 | length 7.9
  TOP w0.3: pad.@282.7,28.3 285.1,30.7 R254.2@285.922,30.7 ; R254.2@286.1,30.878 R253.2@286.1,31.622
  TOP w0.45: R254.2@285.922,30.7 R254.2@286.1,30.7 R254.2@286.1,30.878 ; R253.2@286.1,31.622 R253.2@286.1,31.8
  BOTTOM w0.3: IC251.6@281.155,27.725 282.125,27.725 pad.@282.7,28.3
  BOTTOM w0.4: IC251.6@280.562,27.725 IC251.6@281.155,27.725
SIG00514: IC251.7 pad.@283.4,27.6 R255.2 R256.2 | length 7.2
  TOP w0.3: pad.@283.4,27.6 284.3,28.5 R256.2@285.922,28.5 ; R256.2@286.1,28.678 R255.2@286.1,29.422
  TOP w0.45: R256.2@285.922,28.5 R256.2@286.1,28.5 R256.2@286.1,28.678 ; R255.2@286.1,29.422 R255.2@286.1,29.6
  BOTTOM w0.3: IC251.7@281.324,27.075 282.875,27.075 pad.@283.4,27.6
  BOTTOM w0.4: IC251.7@280.562,27.075 IC251.7@281.324,27.075
SIG00515: IC251.9 pad.@284.3,26.2 R259.2 | length 6.1
  TOP w0.3: pad.@284.3,26.2 285.3,25.2 R259.2@285.922,25.2
  TOP w0.45: R259.2@285.922,25.2 R259.2@286.1,25.2
  BOTTOM w0.3: IC251.9@281.324,25.775 283.875,25.775 pad.@284.3,26.2
  BOTTOM w0.4: IC251.9@280.562,25.775 IC251.9@281.324,25.775
SIG00516: IC251.8 pad.@285.3,26.3 R257.2 R258.2 | length 7.2
  TOP w0.3: pad.@285.3,26.3 R258.2@286.1,26.3 ; R258.2@286.1,26.478 R257.2@286.1,27.222
  TOP w0.45: R258.2@286.1,26.3 R258.2@286.1,26.478 ; R257.2@286.1,27.222 R257.2@286.1,27.4
  BOTTOM w0.3: IC251.8@281.324,26.425 283.425,26.425 284.1,27.1 284.5,27.1 pad.@285.3,26.3
  BOTTOM w0.4: IC251.8@280.562,26.425 IC251.8@281.324,26.425
SIG00517: IC251.12 R280.1 R281.2 R283.2 | length 4.9
  BOTTOM w0.3: IC251.12@280.562,23.668 280.562,23.188 281.525,22.225 R281.2@282.1,22.225 ; R281.2@282.269,22.2 R283.2@283.031,22.2 ; R283.2@283.369,22.2 R280.1@284.397,22.2
  BOTTOM w0.4: R281.2@282.1,22.2 R281.2@282.269,22.2 ; R283.2@283.031,22.2 R283.2@283.369,22.2
  BOTTOM w0.45: R280.1@284.397,22.2 R280.1@284.575,22.2
  BOTTOM w0.6: IC251.12@280.562,23.668 IC251.12@280.562,23.725
SIG00518: IC251.10 R263.1 R264.2 R265.1 | length 4.8
  BOTTOM w0.3: IC251.10@281.157,25.125 281.847,25.125 282.022,24.95 R264.2@282.531,24.95 ; R264.2@282.869,24.95 R265.1@283.997,24.95 ; R263.1@284.175,24.028 R265.1@284.175,24.772
  BOTTOM w0.4: IC251.10@280.562,25.125 IC251.10@281.157,25.125 ; R264.2@282.531,24.95 R264.2@282.869,24.95
  BOTTOM w0.45: R265.1@283.997,24.95 R265.1@284.175,24.95 R265.1@284.175,24.772 ; R263.1@284.175,23.85 R263.1@284.175,24.028
SIG00519: C256.2 C257.2 IC251.4 R285.2 | length 7
  BOTTOM w0.3: IC251.4@281.324,29.025 283.7,29.025 284.1,29.425 C257.2@285.06,29.425 ; C257.2@285.2,29.247 285.2,28.675 C256.2@285.475,28.4 ; R285.2@285.475,27.478 C256.2@285.475,28.222
  BOTTOM w0.4: IC251.4@280.562,29.025 IC251.4@281.324,29.025
  BOTTOM w0.45: C257.2@285.06,29.425 C257.2@285.2,29.425 C257.2@285.2,29.247 ; R285.2@285.475,27.3 R285.2@285.475,27.478 ; C256.2@285.475,28.222 C256.2@285.475,28.4
SIG00520: R287.1 R288.2 R292.2 | length 1.7
  BOTTOM w0.3: R288.2@288.778,32.025 R292.2@290.017,32.025
  BOTTOM w0.45: R288.2@288.6,32.025 R288.2@288.778,32.025
  BOTTOM w0.83: R292.2@290.017,32.025 R292.2@290.3,32.025
SIG00521: R288.1 R289.2
SIG00522: C258.2 R292.1 | length 2.2
  BOTTOM w0.3: C258.2@291.9,30.119 R292.1@291.9,31.423
  BOTTOM w0.8: C258.2@291.9,29.65 C258.2@291.9,30.119
  BOTTOM w0.83: R292.1@291.9,31.423 R292.1@291.9,31.8
SIG00523: R290.1 R291.2
SIG00524: R261.1 R262.2
SIG00525: IC251.11 R261.2 | length 4.5
  BOTTOM w0.3: R261.2@277.825,22.165 277.825,23.175 279.125,24.475 IC251.11@279.801,24.475
  BOTTOM w0.4: IC251.11@279.801,24.475 IC251.11@280.562,24.475
  BOTTOM w0.45: R261.2@277.825,22 R261.2@277.825,22.165
SIG00526: C255.2 DP258.1 IC251.15 pad.@272.9,25.65 R266.2 R274.2 R276.2 R277.1
SIG00527: IC251.13 R266.1 R267.2 R268.1 R269.2 | length 2.2
  BOTTOM w0.3: R268.1@271.825,21.778 R269.2@271.825,22.522 ; R269.2@271.825,22.878 R267.2@271.825,23.622
  BOTTOM w0.45: R268.1@271.825,21.6 R268.1@271.825,21.778 ; R269.2@271.825,22.522 R269.2@271.825,22.7 R269.2@271.825,22.878 ; R267.2@271.825,23.622 R267.2@271.825,23.8
SIG00528: IC251.14 pad.@274.75,22.55 R270.1 R271.2 R274.1 R275.2 | length 12.2
  TOP w0.3: R270.1@270.525,22.678 R275.2@270.525,23.422 ; R275.2@270.525,23.778 R271.2@270.525,24.522 ; R271.2@270.69,24.7 R274.1@271.41,24.7 ; R274.1@271.575,24.522 271.575,23.825 271.85,23.55 273.75,23.55 pad.@274.75,22.55
  TOP w0.45: R270.1@270.525,22.5 R270.1@270.525,22.678 ; R275.2@270.525,23.422 R275.2@270.525,23.6 R275.2@270.525,23.778 ; R271.2@270.525,24.522 R271.2@270.525,24.7 R271.2@270.69,24.7 ; R274.1@271.41,24.7 R274.1@271.575,24.7 R274.1@271.575,24.522
  BOTTOM w0.3: pad.@274.75,22.55 275.75,22.55 276.25,23.05 276.25,24.1 275.875,24.475 IC251.14@275.555,24.475
  BOTTOM w0.4: IC251.14@274.837,24.475 IC251.14@275.555,24.475
SIG00772: R363.1 R364.1 R365.2 | length 2.2
  BOTTOM w0.3: R365.2@257.3,22.478 R363.1@257.3,23.222 ; R365.2@257.478,22.3 R364.1@258.247,22.3
  BOTTOM w0.45: R365.2@257.3,22.478 R365.2@257.3,22.3 R365.2@257.478,22.3 ; R363.1@257.3,23.222 R363.1@257.3,23.4 ; R364.1@258.247,22.3 R364.1@258.425,22.3
SIG00774: IC304.6 R363.2 | length 4.5
  BOTTOM w0.3: IC304.6@253.742,25.095 254.305,25.095 254.65,24.75 254.65,23.9 255.15,23.4 R363.2@256.272,23.4
  BOTTOM w0.45: R363.2@256.272,23.4 R363.2@256.45,23.4
  BOTTOM w0.55: IC304.6@253.12,25.095 IC304.6@253.742,25.095
SIG00777: IC304.3 R354.2 | length 4.6
  BOTTOM w0.3: IC304.3@253.939,28.905 255.245,28.905 256.45,27.7 R354.2@256.45,27.128
  BOTTOM w0.45: R354.2@256.45,26.95 R354.2@256.45,27.128
  BOTTOM w0.55: IC304.3@253.12,28.905 IC304.3@253.939,28.905
SIG00781: R360.1 R361.1 R362.2 | length 3.8
  BOTTOM w0.3: R360.1@257.3,24.55 257.95,24.55 258.4,24.1 258.4,23.625 258.575,23.45 R362.2@259.081,23.45 ; R362.2@259.419,23.45 R361.1@260.197,23.45
  BOTTOM w0.4: R362.2@259.081,23.45 R362.2@259.419,23.45
  BOTTOM w0.45: R361.1@260.197,23.45 R361.1@260.375,23.45
SIG00783: IC304.4 R357.2 | length 4.6
  BOTTOM w0.3: IC304.4@253.881,27.635 254.965,27.635 255.7,26.9 255.7,26.1 256.05,25.75 R357.2@256.41,25.75
  BOTTOM w0.45: R357.2@256.41,25.75 R357.2@256.45,25.75
  BOTTOM w0.55: IC304.4@253.12,27.635 IC304.4@253.881,27.635
SIG00789: R357.1 R358.1 R359.2
SIG00791: IC304.5 R360.2 | length 4.4
  BOTTOM w0.3: IC304.5@253.742,26.365 254.285,26.365 255.35,25.3 255.35,24.8 255.6,24.55 R360.2@256.272,24.55
  BOTTOM w0.45: R360.2@256.272,24.55 R360.2@256.45,24.55
  BOTTOM w0.55: IC304.5@253.12,26.365 IC304.5@253.742,26.365
SIG00794: R354.1 R355.1 R356.2
SIG00797: C310.2 D306.C DP302.1 IC302.5 R312.2 R313.1
SIG00799: IC303.4 R351.2 | length 1.7
  TOP w0.3: IC303.4@254.75,23.33 255.47,23.33 255.5,23.3 R351.2@255.86,23.3
  TOP w0.45: R351.2@255.86,23.3 R351.2@256.025,23.3
  TOP w0.6: IC303.4@254.325,23.33 IC303.4@254.75,23.33
SIG00817: DP404.1 R418.2
SIG00818: DP405.1 R419.2
SIG00819: DP406.1 R420.2
SIG00820: DP407.1 R421.2 | length 3.9
  BOTTOM w0.3: R421.2@198.753,111.2 DP407.1@202.45,111.2
  BOTTOM w0.45: R421.2@198.575,111.2 R421.2@198.753,111.2
SIG00823: C453.2 IC451.5 R454.1 | length 3
  BOTTOM w0.3: R454.1@257.703,33.3 C453.2@258.631,33.3 ; C453.2@258.969,33.3 IC451.5@259.792,33.3
  BOTTOM w0.4: C453.2@258.631,33.3 C453.2@258.969,33.3
  BOTTOM w0.45: R454.1@257.525,33.3 R454.1@257.703,33.3 ; IC451.5@259.792,33.3 IC451.5@260.525,33.3
SIG00826: C452.2 IC451.1 IC451.3 R453.2 | length 8.8
  BOTTOM w0.3: IC451.1@263.217,33.325 C452.2@264.077,33.325 ; IC451.3@263.291,31.313 265.488,31.313 266.275,32.1 R453.2@266.275,33.322 ; C452.2@264.318,33.325 265.125,33.325 265.3,33.5 R453.2@266.097,33.5
  BOTTOM w0.45: C452.2@264.077,33.325 C452.2@264.255,33.325 C452.2@264.318,33.325 ; R453.2@266.097,33.5 R453.2@266.275,33.5 R453.2@266.275,33.322
  BOTTOM w0.5: IC451.1@262.838,33.325 IC451.1@263.217,33.325
  BOTTOM w0.825: IC451.3@262.675,31.313 IC451.3@263.291,31.313
SIG00837: D451.1 D451.3 T401.12 T401.13
SIG00839: C411.2 D404.A D405.C IC402.2 IC402.4 R415.2 R416.2 | length 1.8
  TOP w0.3: C411.2@205.45,70.475 206.375,71.4 R416.2@206.375,71.76
  TOP w0.45: R416.2@206.375,71.76 R416.2@206.375,71.85
SIG00841: D401.A Q401.D T401.3
SIG00842: C402.1 C403.1 D401.C R401.1
SIG00843: D402.A R409.2 R413.2 T401.6
SIG00847: Q401.S R403.1 R404.2 R405.2 R406.2 R407.2 | length 18
  TOP w0.3: Q401.S@223.81,41.45 227.075,38.185 R403.1@227.075,37.628
  TOP w0.45: R403.1@227.075,37.45 R403.1@227.075,37.628
  Mid-Layer 2 w0.3: v1(218.8,36.9) 218.8,32.7 222.35,29.15 v1(224.7,29.15)
  BOTTOM w0.3: v1(224.7,29.15) 225.05,29.15 225.2,29 R407.2@225.56,29
  BOTTOM w0.45: R407.2@225.56,29 R407.2@225.725,29
SIG00848: C407.2 R413.1 | length 1
  BOTTOM w0.3: C407.2@233.69,28.45 R413.1@234.41,28.45
  BOTTOM w0.45: C407.2@233.575,28.45 C407.2@233.69,28.45 ; R413.1@234.41,28.45 R413.1@234.525,28.45
SIG00849: IC401.2 R409.1 R410.2 | length 3
  BOTTOM w0.3: IC401.2@230.316,32.985 R409.1@231.387,32.985 ; R409.1@231.713,32.985 R410.2@232.466,32.985
  BOTTOM w0.37: R409.1@231.387,32.985 R409.1@231.713,32.985
  BOTTOM w0.43: R410.2@232.466,32.985 R410.2@232.64,32.985
  BOTTOM w0.65: IC401.2@229.661,32.985 IC401.2@230.316,32.985
SIG00851: DP402.1 IC401.5 pad.@222.6,30.4 R407.1 | length 10
  TOP w0.3: pad.@222.6,30.4 223.35,30.4 225.15,32.2 DP402.1@225.15,34
  BOTTOM w0.3: pad.@222.6,30.4 IC401.5@223.6,30.4 ; IC401.5@224.894,30.445 225.755,30.445 226.575,29.625 R407.1@226.575,29
  BOTTOM w0.56: IC401.5@223.6,30.4 IC401.5@224.194,30.4
  BOTTOM w0.65: IC401.5@224.239,30.445 IC401.5@224.894,30.445
SIG00852: C451.2 D451.2 R451.2 R452.1
SIG00853: C401.2 C402.2 C403.2 F401.2 IC401.7 R401.2 T401.1
SIG00854: IC401.3 R412.2 | length 2
  BOTTOM w0.3: IC401.3@230.1,31.715 230.91,31.715 R412.2@231.45,31.175
  BOTTOM w0.65: IC401.3@229.661,31.715 IC401.3@230.1,31.715
SIG00855: D402.C R408.2
SIG00856: C405.2 DP401.1 IC401.1 pad.@231.1,35.25 R408.1 | length 3.1
  TOP w0.3: DP401.1@228.4,34.4 230.25,34.4 pad.@231.1,35.25
SIG00858: C412.2 IC403.1 IC403.3 R417.2
SIG00859: D403.A T401.5 | length 38
  TOP w0.5: D403.A@218.031,60.506 229.094,60.506 231.95,57.65 231.95,43.2 235.5,39.65 T401.5@238.5,39.65
  TOP w1.2: D403.A@217.65,60.506 D403.A@218.031,60.506
SIG00860: C408.2 C409.2 D403.C D404.C IC402.3
SIG00861: R410.1 R411.2 | length 1
  BOTTOM w0.3: R411.2@232.65,31.29 R410.1@232.65,32.01
  BOTTOM w0.45: R411.2@232.65,31.175 R411.2@232.65,31.29 ; R410.1@232.65,32.01 R410.1@232.65,32.125
SIG00862: C410.2 D405.A IC402.1 R414.2 R415.1
SIG00863: IC401.6 R402.1 | length 6.9
  Mid-Layer 2 w0.5: v1(222.55,31.7) 222.55,35.65 v1(224.65,37.75)
SIG00864: Q401.G R402.2 R403.2 | length 4.4
  TOP w0.3: R403.2@227.925,37.45 228.89,38.415 Q401.G@228.89,41.45
SIG007100: C304.2 C305.2 IC301.1 | length 2.8
  BOTTOM w0.3: C305.2@145.278,27.775 C304.2@146.222,27.775 ; C304.2@146.578,27.775 IC301.1@147.781,27.775
  BOTTOM w0.4: IC301.1@147.781,27.775 IC301.1@147.95,27.775
  BOTTOM w0.45: C305.2@145.1,27.775 C305.2@145.278,27.775 ; C304.2@146.222,27.775 C304.2@146.4,27.775 C304.2@146.578,27.775
SIG007101: IC303.3 R317.2 | length 2.4
  TOP w0.3: R317.2@244.203,21.9 244.95,21.9 245.175,22.125 IC303.3@245.175,23.207
  TOP w0.45: R317.2@244.025,21.9 R317.2@244.203,21.9
  TOP w0.6: IC303.3@245.175,23.207 IC303.3@245.175,23.33
SIG007102: D304.A R308.2 | length 4.2
  BOTTOM w0.3: D304.A@153,29.8 153,30.567 cw(c153.2,30.567) 153.059,30.709 154.192,31.842 cw(c154.333,31.7) 154.333,31.9 R308.2@155.487,31.9
  BOTTOM w0.4: D304.A@153,29.6 D304.A@153,29.8
  BOTTOM w0.45: R308.2@155.487,31.9 R308.2@155.675,31.9
SIG007103: IC303.1 Q301.D R316.1 | length 4.7
  TOP w0.3: Q301.D@242.85,23.587 242.85,24.1 243.05,24.3 R316.1@243.05,25.59 ; R316.1@243.257,25.87 IC303.1@244.544,25.87
  TOP w0.5: Q301.D@242.85,23.4 Q301.D@242.85,23.587
  TOP w0.6: IC303.1@244.544,25.87 IC303.1@245.175,25.87
  TOP w0.73: R316.1@243,25.87 R316.1@243.257,25.87
  TOP w0.83: R316.1@243.05,25.59 R316.1@243.05,25.85
SIG007104: C303.2 IC301.3
SIG007105: Q351.G R351.1 R352.2 | length 2.2
  TOP w0.3: R352.2@256.85,22.415 R351.1@256.85,23.175 ; R352.2@257.028,22.275 Q351.G@257.875,22.275
  TOP w0.4: R351.1@256.85,23.175 R351.1@256.85,23.275 ; Q351.G@257.875,22.275 Q351.G@258.05,22.275
  TOP w0.45: R352.2@256.85,22.415 256.85,22.275 R352.2@257.028,22.275
SIG007106: D303.A R307.2 | length 2.2
  BOTTOM w0.3: R307.2@146.3,24.975 147.175,24.1 D303.A@147.175,23.16
  BOTTOM w0.55: D303.A@147.175,23.1 D303.A@147.175,23.16
SIG007109: R305.1 R306.2
SIG007110: R310.2 R311.1
SIG007111: R303.2 R304.1
SIG007112: C306.2 DP303.1 IC302.3 pad.@229.5,23.7 Q303.D
SIG007115: R311.2 R313.2 | length 43.3
  TOP w0.3: R313.2@236.925,26.6 237.375,26.6 ccw(c237.375,26.721) 237.46,26.635 v1(238.125,27.3)
  Mid-Layer 2 w0.3: v1(238.125,27.3) 239.8,27.3 248.75,36.25 v1(248.75,63.75)
SIG007116: C307.2 C308.2 IC302.1 | length 2.6
  TOP w0.3: C308.2@234.675,23 235.1,23 235.425,23.325 IC302.1@235.881,23.325 ; C308.2@234.675,23.178 C307.2@234.675,23.922
  TOP w0.4: IC302.1@235.881,23.325 IC302.1@236.05,23.325
  TOP w0.45: C308.2@234.675,23 C308.2@234.675,23.178 ; C307.2@234.675,23.922 C307.2@234.675,24.1
SIG007118: Q351.D R353.1 | length 1.7
  TOP w0.3: Q351.D@258.637,23.65 R353.1@259.947,23.65
  TOP w0.45: R353.1@259.947,23.65 R353.1@260.125,23.65
  TOP w0.5: Q351.D@258.45,23.65 Q351.D@258.637,23.65
SIG007120: R309.2 R310.1
SIG007121: R301.2 R302.1
SIG007122: R302.2 R303.1
SIG007123: C302.2 D302.C D305.C DP301.1 IC301.5 pad.@145.2,26.2 R304.2 R305.2 R307.1 | length 5.8
  BOTTOM w0.3: D302.C@140.675,30.403 140.675,29.025 141.925,27.775 C302.2@142.522,27.775 ; R307.1@146.478,25.825 IC301.5@147.781,25.825
  BOTTOM w0.4: IC301.5@147.781,25.825 IC301.5@147.95,25.825
  BOTTOM w0.45: C302.2@142.522,27.775 C302.2@142.7,27.775 ; R307.1@146.3,25.825 R307.1@146.478,25.825
  BOTTOM w0.55: D302.C@140.675,30.403 D302.C@140.675,30.6
SIG007124: IC302.4 Q301.G R314.1 R315.2 | length 2.9
  TOP w0.3: R315.2@240.1,24.003 R314.1@240.1,25.097 ; R315.2@240.275,23.8 Q301.G@241.131,23.8
  TOP w0.4: R315.2@240.1,23.8 R315.2@240.275,23.8 ; Q301.G@241.131,23.8 Q301.G@241.55,23.8
  TOP w0.45: R315.2@240.1,23.825 R315.2@240.1,24.003 ; R314.1@240.1,25.097 R314.1@240.1,25.275
SIG007125: Q302.D Q303.G R318.1 R319.2 | length 81.9
  Mid-Layer 3 w0.3: v1(153.4,22.65) 155.05,24.3 157.25,24.3 159.6,21.95 161.85,21.95 162.6,22.7 171.25,22.7 171.9,23.35 179.5,23.35 181.85,21 212.55,21 214.5,22.95 223.55,22.95 v1(227.8,27.2)
  BOTTOM w0.3: Q302.D@151.9,22.65 v1(153.4,22.65)
  BOTTOM w0.5: Q302.D@151.7,22.65 Q302.D@151.9,22.65
SIG007126: D305.A R320.1 R321.2 | length 2.8
  TOP w0.3: R320.1@142.3,25.412 D305.A@142.3,26.325 ; D305.A@142.3,26.675 R321.2@142.3,27.788
  TOP w0.4: D305.A@142.3,26.325 D305.A@142.3,26.5 D305.A@142.3,26.675
  TOP w0.45: R320.1@142.3,25.225 R320.1@142.3,25.412 ; R321.2@142.3,27.788 R321.2@142.3,27.975
SIG007127: D306.A R322.1 R323.2
SIGN254: D66.A R66.1 | length 2.1
  TOP w0.3: D66.A@177.727,68.5 R66.1@178.997,68.5
  TOP w0.45: R66.1@178.997,68.5 R66.1@179.175,68.5
  TOP w0.55: D66.A@177.125,68.5 D66.A@177.727,68.5
SIGN255: D61.A R58.1 | length 2.1
  TOP w0.3: R58.1@155.003,67.7 D61.A@156.273,67.7
  TOP w0.45: R58.1@154.825,67.7 R58.1@155.003,67.7
  TOP w0.55: D61.A@156.273,67.7 D61.A@156.875,67.7
SIGN266: C81.2 DP55.1 L54.2 Q52.G R64.2 | length 1.1
  TOP w0.3: R64.2@172.925,74.128 C81.2@172.925,74.872
  TOP w0.45: R64.2@172.925,73.95 R64.2@172.925,74.128 ; C81.2@172.925,74.872 C81.2@172.925,75.05
SIGN267: C82.2 DP53.1 L53.2 Q51.G R56.2 | length 1.1
  TOP w0.3: R56.2@143.825,68.978 C82.2@143.825,69.722
  TOP w0.45: R56.2@143.825,68.8 R56.2@143.825,68.978 ; C82.2@143.825,69.722 C82.2@143.825,69.9
SS/EN: C251.2 IC251.5 R252.2 R353.2 | length 32.2
  TOP w0.3: R353.2@261.127,23.65 261.75,23.65 262.8,24.7 v1(262.8,26.65)
  TOP w0.45: R353.2@260.975,23.65 R353.2@261.127,23.65
  Mid-Layer 2 w0.3: v1(262.8,26.65) 263.25,26.2 267.9,26.2 271.7,30 271.7,32.85 273.2,34.35 v1(275.65,34.35)
  BOTTOM w0.3: C251.2@275.65,32.578 R252.2@275.65,33.322 ; R252.2@275.65,33.55 v1(275.65,34.35) ; C251.2@275.828,32.4 277.1,32.4 278.3,31.2 278.3,28.875 278.8,28.375 IC251.5@279.801,28.375
  BOTTOM w0.4: IC251.5@279.801,28.375 IC251.5@280.562,28.375
  BOTTOM w0.45: C251.2@275.65,32.578 C251.2@275.65,32.4 C251.2@275.828,32.4 ; R252.2@275.65,33.322 R252.2@275.65,33.5 R252.2@275.65,33.55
